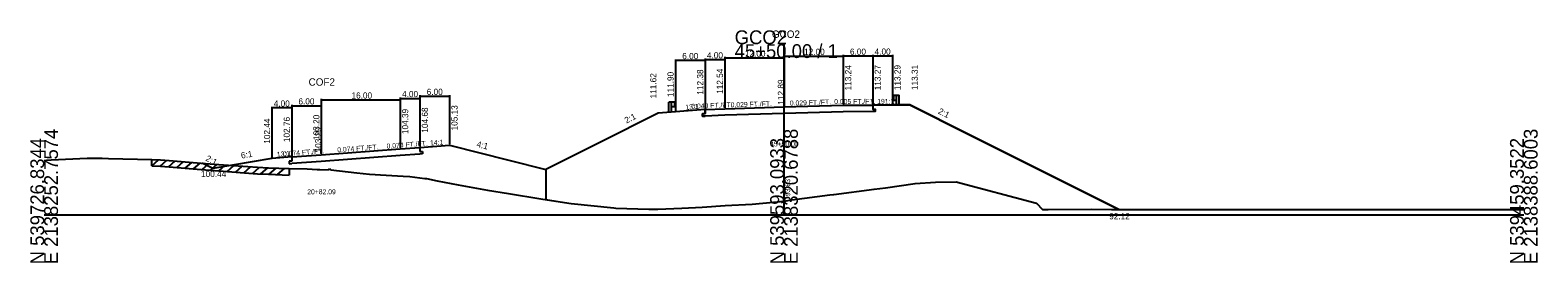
# Model space of a CAD drawing. Extents: x -14327 to 8886, y -10 to 39048.
# Drawn here: x 997.2 to 1302.8, y 30990.3 to 31037.4 of the extents above; entities that cross this region are included whole.
import ezdxf

# ---------------------------------------------------------------- set-up
doc = ezdxf.new("R2010")
doc.units = 0
for name, color, linetype in [('Level 1', 7, 'Continuous'), ('Level 20', 7, 'Continuous'), ('Level 5', 7, 'Continuous'), ('Level 53', 7, 'Continuous'), ('Level 54', 7, 'Continuous'), ('Level 55', 7, 'Continuous'), ('Level 7', 7, 'Continuous'), ('RD_GPK_XS_Cell', 7, 'Continuous'), ('RD_XS_EwShp', 7, 'Continuous'), ('RD_XS_ExGround', 7, 'Continuous'), ('RD_XS_ExPaveRet', 7, 'Continuous'), ('RD_XS_Pave', 7, 'Continuous'), ('RD_XS_TX_Baseline', 7, 'Continuous'), ('RD_XS_TX_Elev_EX', 7, 'Continuous'), ('RD_XS_TX_Elev_PR', 7, 'Continuous'), ('RD_XS_TX_Station', 7, 'Continuous')]:
    doc.layers.add(name, color=color, linetype=linetype)

msp = doc.modelspace()

# ---------------------------------------------------------------- linework, layer by layer
at = {"layer": 'Level 1'}
for p, q in [((1172.02, 31024.11), (1172.14, 31024.2)), ((1172.02, 31024.01), (1172.14, 31023.91)), ((1172.02, 31023.58), (1172.14, 31023.67)), ((1172.15, 31024.2), (1172.23, 31024.22)), ((1172.16, 31023.87), (1172.16, 31023.71)), ((1172.23, 31024.28), (1172.23, 31023.3)), ((1172.23, 31024.28), (1172.78, 31024.28)), ((1172.78, 31022.29), (1172.78, 31024.28)), ((1172.78, 31024.28), (1173.34, 31024.28)), ((1173.34, 31022.29), (1173.34, 31024.28)), ((1126.66, 31020.9), (1126.66, 31022.89)), ((1127.22, 31022.89), (1126.66, 31022.89)), ((1127.22, 31020.9), (1127.22, 31022.89)), ((1127.77, 31022.89), (1127.22, 31022.89)), ((1127.77, 31021.91), (1127.22, 31021.91)), ((1127.77, 31022.89), (1127.77, 31021.91)), ((1127.85, 31022.81), (1127.77, 31022.83)), ((1127.85, 31021.99), (1127.77, 31021.98)), ((1127.84, 31022.48), (1127.84, 31022.32)), ((1127.98, 31022.72), (1127.86, 31022.81)), ((1127.98, 31022.62), (1127.86, 31022.52)), ((1127.98, 31022.19), (1127.86, 31022.28)), ((1127.98, 31022.09), (1127.86, 31021.99)), ((1172.02, 31023.48), (1172.14, 31023.38)), ((1172.15, 31023.38), (1172.23, 31023.37)), ((1172.23, 31023.3), (1172.78, 31023.3))]:
    msp.add_line(p, q, dxfattribs=at)
for centre, radius, start, end in [((1172.07, 31024.06), 0.0651, 129.0336, 230.9663), ((1172.09, 31023.71), 0.0651, 302.9895, 0), ((1172.15, 31024.18), 0.026, 90, 129.0505), ((1172.09, 31023.87), 0.0651, 0, 45), ((1127.91, 31022.48), 0.0651, 135, 180), ((1127.91, 31022.32), 0.0651, 180, 237.0105), ((1127.85, 31022.79), 0.026, 50.9495, 90), ((1127.85, 31022.01), 0.026, 270, 309.0504), ((1127.93, 31022.67), 0.0651, 309.0337, 50.9664), ((1127.93, 31022.14), 0.0651, 309.0337, 50.9664), ((1172.07, 31023.53), 0.0651, 129.0336, 230.9663), ((1172.15, 31023.4), 0.026, 230.9496, 270)]:
    msp.add_arc(centre, radius, start, end, dxfattribs=at)
at = {"layer": 'Level 20'}
for p, q in [((1072.19, 31023.83), (1072.19, 31013.59)), ((1072.19, 31023.63), (1076.19, 31023.63)), ((1076.19, 31024.28), (1076.19, 31013.88)), ((1076.19, 31024.08), (1082.19, 31024.08)), ((1076.19, 31023.83), (1076.19, 31013.88)), ((1082.19, 31024.28), (1082.19, 31014.33)), ((1046.18, 31021.91), (1046.18, 31011.64)), ((1050.18, 31021.71), (1046.18, 31021.71)), ((1050.18, 31022.35), (1050.18, 31011.96)), ((1050.18, 31022.15), (1056.18, 31022.15)), ((1050.18, 31021.91), (1050.18, 31011.96)), ((1056.18, 31023.54), (1056.18, 31012.4)), ((1056.18, 31023.34), (1072.19, 31023.34)), ((1056.18, 31022.35), (1056.18, 31012.4)), ((1072.19, 31023.54), (1072.19, 31013.59)), ((1046.18, 31011.44), (1034.18, 31009.44)), ((1050.18, 31011.76), (1046.18, 31011.44)), ((1050.18, 31011.76), (1056.18, 31012.2)), ((1050.18, 31011.76), (1050.18, 31010.92)), ((1056.18, 31012.2), (1072.19, 31013.39)), ((1072.19, 31012.05), (1056.18, 31010.87)), ((1072.19, 31013.39), (1076.19, 31013.68)), ((1076.19, 31012.35), (1072.19, 31012.05)), ((1076.19, 31013.68), (1082.19, 31014.13)), ((1076.19, 31013.68), (1076.19, 31012.85)), ((1076.19, 31012.85), (1076.69, 31012.89)), ((1076.69, 31012.39), (1076.19, 31012.35)), ((1076.69, 31012.89), (1076.69, 31012.39)), ((1082.19, 31014.13), (1094.19, 31011.13)), ((1034.18, 31009.44), (1032.05, 31010.5)), ((1050.18, 31010.92), (1049.68, 31010.89)), ((1049.68, 31010.89), (1049.68, 31010.39)), ((1049.68, 31010.39), (1050.18, 31010.42)), ((1056.18, 31010.87), (1050.18, 31010.42)), ((1094.19, 31011.13), (1101.74, 31009.24))]:
    msp.add_line(p, q, dxfattribs=at)
at = {"layer": 'Level 5'}
for p, q in [((1134, 31021.38), (1134, 31020.55)), ((1162, 31020.9), (1150, 31020.56)), ((1168, 31020.94), (1162, 31020.9)), ((1168, 31022.27), (1168, 31021.44)), ((1168, 31021.44), (1168.5, 31021.44)), ((1168.5, 31020.94), (1168, 31020.94)), ((1168.5, 31021.44), (1168.5, 31020.94)), ((1134, 31020.55), (1133.5, 31020.53)), ((1133.5, 31020.53), (1133.5, 31020.03)), ((1133.5, 31020.03), (1134, 31020.05)), ((1138, 31020.21), (1134, 31020.05)), ((1150, 31020.56), (1138, 31020.21))]:
    msp.add_line(p, q, dxfattribs=at)
at = {"layer": 'Level 54'}
for p, q in [((1128, 31031.53), (1128, 31021.1)), ((1134, 31031.33), (1128, 31031.33)), ((1134, 31031.69), (1134, 31021.58)), ((1134, 31031.53), (1134, 31021.58)), ((1134, 31031.49), (1138, 31031.49)), ((1138, 31032.04), (1138, 31021.74)), ((1138, 31031.84), (1150, 31031.84)), ((1138, 31031.69), (1138, 31021.74)), ((1150, 31032.39), (1150, 31022.09)), ((1150, 31032.19), (1162, 31032.19)), ((1150, 31032.04), (1150, 31022.09)), ((1162, 31032.42), (1162, 31022.44)), ((1162, 31032.39), (1162, 31022.44)), ((1162, 31032.22), (1168, 31032.22)), ((1168, 31032.44), (1168, 31022.47)), ((1168, 31032.42), (1168, 31022.47)), ((1168, 31032.24), (1172, 31032.24)), ((1172, 31032.44), (1172, 31022.49))]:
    msp.add_line(p, q, dxfattribs=at)
at = {"layer": 'Level 7'}
for p, q in [((1124.5, 31020.62), (1112.5, 31014.62)), ((1128, 31020.9), (1124.5, 31020.62)), ((1134, 31021.38), (1128, 31020.9)), ((1168, 31022.27), (1172, 31022.29)), ((1172, 31022.29), (1175.5, 31022.31)), ((1175.5, 31022.31), (1187.5, 31016.31)), ((1112.5, 31014.62), (1101.74, 31009.24)), ((1187.5, 31016.31), (1217.88, 31001.12)), ((1101.74, 31009.24), (1101.74, 31003.11))]:
    msp.add_line(p, q, dxfattribs=at)
at = {"layer": 'RD_GPK_XS_Cell'}
for p, q in [((1150, 31000), (1150, 31034.61)), ((1000, 31000), (1150, 31000)), ((1150, 31000), (1300, 31000))]:
    msp.add_line(p, q, dxfattribs=at)
at = {"layer": 'RD_XS_EwShp'}
msp.add_lwpolyline([(1101.74, 31003.11), (1104.65, 31002.69), (1106.83, 31002.31), (1115.5, 31001.43), (1115.88, 31001.41), (1122.62, 31001.2), (1123.42, 31001.16), (1124.45, 31001.18), (1129.29, 31001.36), (1133.42, 31001.61), (1138.06, 31001.91), (1143.55, 31002.21), (1150, 31002.83), (1151.57, 31003.05), (1159.27, 31004.06), (1160.12, 31004.18), (1168.27, 31005.24), (1170.57, 31005.52), (1176.56, 31006.36), (1180.71, 31006.64), (1184.88, 31006.7), (1201.21, 31002.42), (1202.38, 31001.12), (1203.57, 31001.12), (1212.26, 31001.15), (1216.37, 31001.12), (1217.88, 31001.12), (1187.5, 31016.31), (1175.5, 31022.31), (1172, 31022.29), (1168, 31022.27), (1168, 31021.44), (1168.5, 31021.44), (1168.5, 31020.94), (1168, 31020.94), (1162, 31020.9), (1150, 31020.56), (1138, 31020.21), (1134, 31020.05), (1133.5, 31020.03), (1133.5, 31020.53), (1134, 31020.55), (1134, 31021.38), (1128, 31020.9), (1124.5, 31020.62), (1112.5, 31014.62), (1101.74, 31009.24)], close=True, dxfattribs=at)
at = {"layer": 'RD_XS_ExGround'}
for p, q in [((1001.45, 31011.16), (1008.75, 31011.5)), ((1008.75, 31011.5), (1011.77, 31011.54)), ((1011.77, 31011.54), (1013.01, 31011.43)), ((1013.01, 31011.43), (1021.81, 31011.27)), ((1000, 31011.07), (1000.48, 31011.11)), ((1000.48, 31011.11), (1001.45, 31011.16)), ((1021.81, 31011.27), (1023.58, 31011.16)), ((1023.58, 31011.16), (1025.33, 31011.05)), ((1025.33, 31011.05), (1031.81, 31010.52)), ((1031.81, 31010.52), (1035.41, 31010.25)), ((1035.41, 31010.25), (1043.24, 31009.66)), ((1043.24, 31009.66), (1045.47, 31009.57)), ((1045.47, 31009.57), (1049.69, 31009.39)), ((1049.69, 31009.39), (1053.29, 31009.32)), ((1053.29, 31009.32), (1055.34, 31009.19)), ((1055.34, 31009.19), (1055.87, 31009.19)), ((1055.87, 31009.19), (1057.66, 31009.17)), ((1057.66, 31009.17), (1057.82, 31009.4)), ((1057.82, 31009.4), (1058.11, 31009.15)), ((1058.11, 31009.15), (1063.4, 31008.52)), ((1063.4, 31008.52), (1065.97, 31008.28)), ((1065.97, 31008.28), (1069.31, 31008.08)), ((1069.31, 31008.08), (1072.76, 31007.89)), ((1072.76, 31007.89), (1074.13, 31007.79)), ((1074.13, 31007.79), (1076.15, 31007.54)), ((1076.15, 31007.54), (1077.16, 31007.4)), ((1077.16, 31007.4), (1077.53, 31007.37)), ((1077.53, 31007.37), (1079.7, 31006.93)), ((1079.7, 31006.93), (1083.93, 31006.11)), ((1083.93, 31006.11), (1089.9, 31005.04)), ((1168.27, 31005.24), (1170.57, 31005.52)), ((1170.57, 31005.52), (1176.56, 31006.36)), ((1176.56, 31006.36), (1180.71, 31006.64)), ((1180.71, 31006.64), (1184.88, 31006.7)), ((1184.88, 31006.7), (1201.21, 31002.42)), ((1089.9, 31005.04), (1094.15, 31004.38)), ((1094.15, 31004.38), (1100.7, 31003.27)), ((1100.7, 31003.27), (1104.65, 31002.69)), ((1104.65, 31002.69), (1106.83, 31002.31)), ((1106.83, 31002.31), (1115.5, 31001.43)), ((1143.55, 31002.21), (1150, 31002.83)), ((1150, 31002.83), (1151.57, 31003.05)), ((1151.57, 31003.05), (1159.27, 31004.06)), ((1159.27, 31004.06), (1160.12, 31004.18)), ((1160.12, 31004.18), (1168.27, 31005.24)), ((1201.21, 31002.42), (1202.38, 31001.12)), ((1115.5, 31001.43), (1115.88, 31001.41)), ((1115.88, 31001.41), (1122.62, 31001.2)), ((1122.62, 31001.2), (1123.42, 31001.16)), ((1123.42, 31001.16), (1124.45, 31001.18)), ((1124.45, 31001.18), (1129.29, 31001.36)), ((1129.29, 31001.36), (1133.42, 31001.61)), ((1133.42, 31001.61), (1138.06, 31001.91)), ((1138.06, 31001.91), (1143.55, 31002.21)), ((1202.38, 31001.12), (1203.57, 31001.12)), ((1203.57, 31001.12), (1212.26, 31001.15)), ((1212.26, 31001.15), (1216.37, 31001.12)), ((1216.37, 31001.12), (1226.64, 31001.12)), ((1226.64, 31001.12), (1235.6, 31001.11)), ((1235.6, 31001.11), (1290.45, 31001.11)), ((1290.45, 31001.11), (1300, 31001.1))]:
    msp.add_line(p, q, dxfattribs=at)
at = {"layer": 'RD_XS_ExPaveRet'}
for p, q in [((1021.81, 31009.97), (1021.81, 31011.27)), ((1021.81, 31009.97), (1023.19, 31011.18)), ((1021.81, 31009.97), (1023.58, 31009.86)), ((1023.51, 31009.86), (1024.89, 31011.08)), ((1023.58, 31009.86), (1025.33, 31009.75)), ((1025.21, 31009.76), (1026.56, 31010.95)), ((1025.33, 31009.75), (1031.81, 31009.22)), ((1026.91, 31009.62), (1028.26, 31010.81)), ((1028.61, 31009.48), (1029.96, 31010.67)), ((1030.31, 31009.34), (1031.66, 31010.53)), ((1031.81, 31009.22), (1035.41, 31008.95)), ((1032.01, 31009.2), (1033.37, 31010.4)), ((1033.71, 31009.08), (1035.07, 31010.28)), ((1035.41, 31008.95), (1036.76, 31010.15)), ((1035.41, 31008.95), (1043.24, 31008.36)), ((1037.11, 31008.82), (1038.46, 31010.02)), ((1038.81, 31008.69), (1040.16, 31009.89)), ((1040.51, 31008.56), (1041.86, 31009.76)), ((1042.21, 31008.43), (1043.58, 31009.64)), ((1043.24, 31008.36), (1045.47, 31008.27)), ((1043.91, 31008.33), (1045.32, 31009.57)), ((1045.61, 31008.26), (1047.01, 31009.5)), ((1047.31, 31008.19), (1048.71, 31009.43)), ((1049.69, 31009.39), (1049.69, 31008.09)), ((1045.47, 31008.27), (1049.69, 31008.09))]:
    msp.add_line(p, q, dxfattribs=at)
at = {"layer": 'RD_XS_Pave'}
for p, q in [((1134, 31021.38), (1138, 31021.54)), ((1138, 31021.54), (1150, 31021.89)), ((1150, 31021.89), (1162, 31022.24)), ((1162, 31022.24), (1168, 31022.27))]:
    msp.add_line(p, q, dxfattribs=at)

# ---------------------------------------------------------------- texts
at = {"layer": 'Level 20'}
for s, height, p in [('COF2', 1.5, (1053.61, 31026.2)), ('6.00', 1.25, (1051.55, 31022.4)), ('16.00', 1.25, (1062.31, 31023.59)), ('4.00', 1.25, (1072.56, 31023.88)), ('6.00', 1.25, (1077.56, 31024.33)), ('4.00', 1.25, (1046.55, 31021.96)), ('100.44', 1.25, (1031.8, 31007.69)), ('20+82.09', 1, (1053.33, 31004.2))]:
    msp.add_text(s, height=height, dxfattribs=at).set_placement(p)
for s, height, rotation, p in [('104.39', 1.25, 90, (1073.81, 31016.39)), ('104.68', 1.25, 90, (1077.81, 31016.68)), ('105.13', 1.25, 90, (1083.81, 31017.13)), ('102.44', 1.25, 90, (1045.81, 31014.44)), ('102.76', 1.25, 90, (1049.81, 31014.76)), ('103.20', 1.25, 90, (1055.81, 31015.2)), (' 103.20', 1.25, 90, (1056.18, 31012.2)), ('0.074 FT./FT.', 1, 4.236, (1069.46, 31013.44)), ('14:1', 1, 4.2352, (1078.27, 31014.09)), ('4:1', 1.25, 345.9665, (1087.58, 31013.81)), ('2:1', 1.25, 333.4403, (1032.61, 31011.06)), ('6:1', 1.25, 9.4601, (1040.01, 31011.42)), ('13:1', 1, 4.5729, (1047.21, 31011.77)), ('0.074 FT./FT.', 1, 4.2366, (1048.46, 31011.88)), ('0.074 FT./FT.', 1, 4.2363, (1059.46, 31012.69))]:
    msp.add_text(s, height=height, rotation=rotation, dxfattribs=at).set_placement(p)
at = {"layer": 'Level 53'}
for s, rotation, p in [('113.24', 90, (1163.62, 31025.24)), ('113.27', 90, (1169.62, 31025.27)), ('113.29', 90, (1173.62, 31025.29)), ('113.31', 90, (1177.12, 31025.31)), ('111.62', 90, (1124.12, 31023.62)), ('111.90', 90, (1127.62, 31023.9)), ('112.38', 90, (1133.62, 31024.38)), ('112.54', 90, (1137.62, 31024.54)), ('2:1', 333.4349, (1181.11, 31020.62)), ('2:1', 26.5651, (1118.05, 31018.51))]:
    msp.add_text(s, height=1.25, rotation=rotation, dxfattribs=at).set_placement(p)
msp.add_text('92.12', height=1.25, dxfattribs=at).set_placement((1215.93, 30999.12))
at = {"layer": 'Level 54'}
for s, p in [('6.00', (1129.37, 31031.58)), ('4.00', (1134.37, 31031.74)), ('12.00', (1142.07, 31032.09)), ('12.00', (1154.07, 31032.44)), ('6.00', (1163.37, 31032.47)), ('4.00', (1168.37, 31032.49))]:
    msp.add_text(s, height=1.25, dxfattribs=at).set_placement(p)
at = {"layer": 'Level 55'}
for s, rotation, p in [('13:1', 4.5739, (1130.03, 31021.31)), ('0.040 FT./FT.', 2.2906, (1131.22, 31021.52)), ('0.029 FT./FT.', 1.6656, (1139.2, 31021.82)), ('0.029 FT./FT.', 1.6656, (1151.2, 31022.17)), ('0.005 FT./FT.', 0.2999, (1160.18, 31022.48)), ('191:1', 0.2999, (1168.9, 31022.52))]:
    msp.add_text(s, height=1, rotation=rotation, dxfattribs=at).set_placement(p)
at = {"layer": 'RD_GPK_XS_Cell'}
for s, p in [('GCO2', (1140, 31034.61)), ('45+50.00 / 1', (1140, 31031.81))]:
    msp.add_text(s, height=2.8, dxfattribs=at).set_placement(p)
for s, p in [('N 539726.8344', (1000, 30990)), ('E 2138252.7574', (1002.8, 30990)), ('N 539593.0933', (1150, 30990)), ('E 2138320.6788', (1152.8, 30990)), ('N 539459.3522', (1300, 30990)), ('E 2138388.6003', (1302.8, 30990))]:
    msp.add_text(s, height=2.8, rotation=90, dxfattribs=at).set_placement(p)
at = {"layer": 'RD_XS_TX_Baseline'}
msp.add_text('GCO2', height=1.5, dxfattribs=at).set_placement((1147.55, 31035.89))
at = {"layer": 'RD_XS_TX_Elev_EX'}
msp.add_text('93.83', height=1, rotation=90, dxfattribs=at).set_placement((1151.25, 31003.83))
at = {"layer": 'RD_XS_TX_Elev_PR'}
msp.add_text(' 112.89', height=1.25, rotation=90, dxfattribs=at).set_placement((1150, 31021.89))
at = {"layer": 'RD_XS_TX_Station'}
msp.add_text('45+50.00', height=1, dxfattribs=at).set_placement((1147.18, 31013.89))

doc.saveas('drawing.dxf')
